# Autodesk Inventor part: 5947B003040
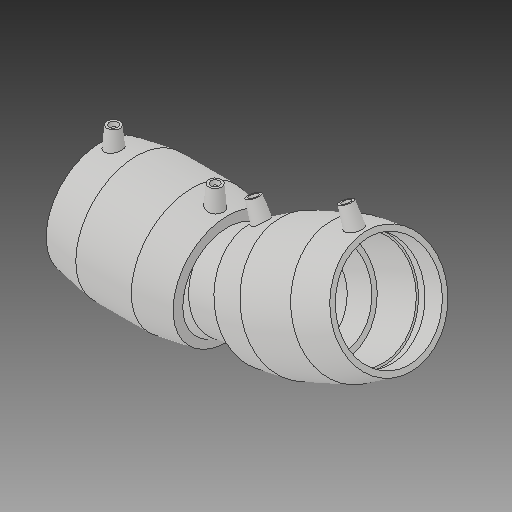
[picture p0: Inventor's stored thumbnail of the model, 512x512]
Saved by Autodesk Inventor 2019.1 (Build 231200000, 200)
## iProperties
Created: 2017-06
Part Number: 5947B003040
Material: Generic
Description: PLASSON ADJUSTABLE ELBOW ASTM 4''
Document SubType Name: Modeling
Designer: KIM
Mass: 16853.5 g
Surface Area: 12350.1 cm^2
Volume: 16853.5 cm^3
Density: 1 g/cm^3
Appearance: Default
Author: KIM
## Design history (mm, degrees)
derived "5947B.ipt"
feature "Solid1::5947B.ipt"
tag "TaggingFeature1"
body "Solid1"
other parameters: "d0" = 145.9992, "d2" = 139.954, "d3" = 82.042, "d4" = 41.021, "d5" = 125.9586, "d7" = 114.1, "d8" = 168 deg, "d10" = 32.8168, "d11" = 10.93893, "d29" = 87.884, "d30" = 15, "d31" = 58.39968, "d34" = 5 deg, "d41" = 4, "d42" = 14, "d43" = 0, "d48" = 102.69, "d49" = 24 deg, "d50" = 364.998, "d51" = 78 deg, "d52" = 90 deg, "d55" = 31.9786, "d57" = 168 deg, "d58" = 6.39572, "d60" = 41.13067, "d62" = 3, "d63" = 0, "d_" = 114.1, "L_" = 364.998, "L_1" = 82.042, "D_" = 139.954, "A_" = 87.884, "d54" = 63.9572, "d59" = 137.10223
